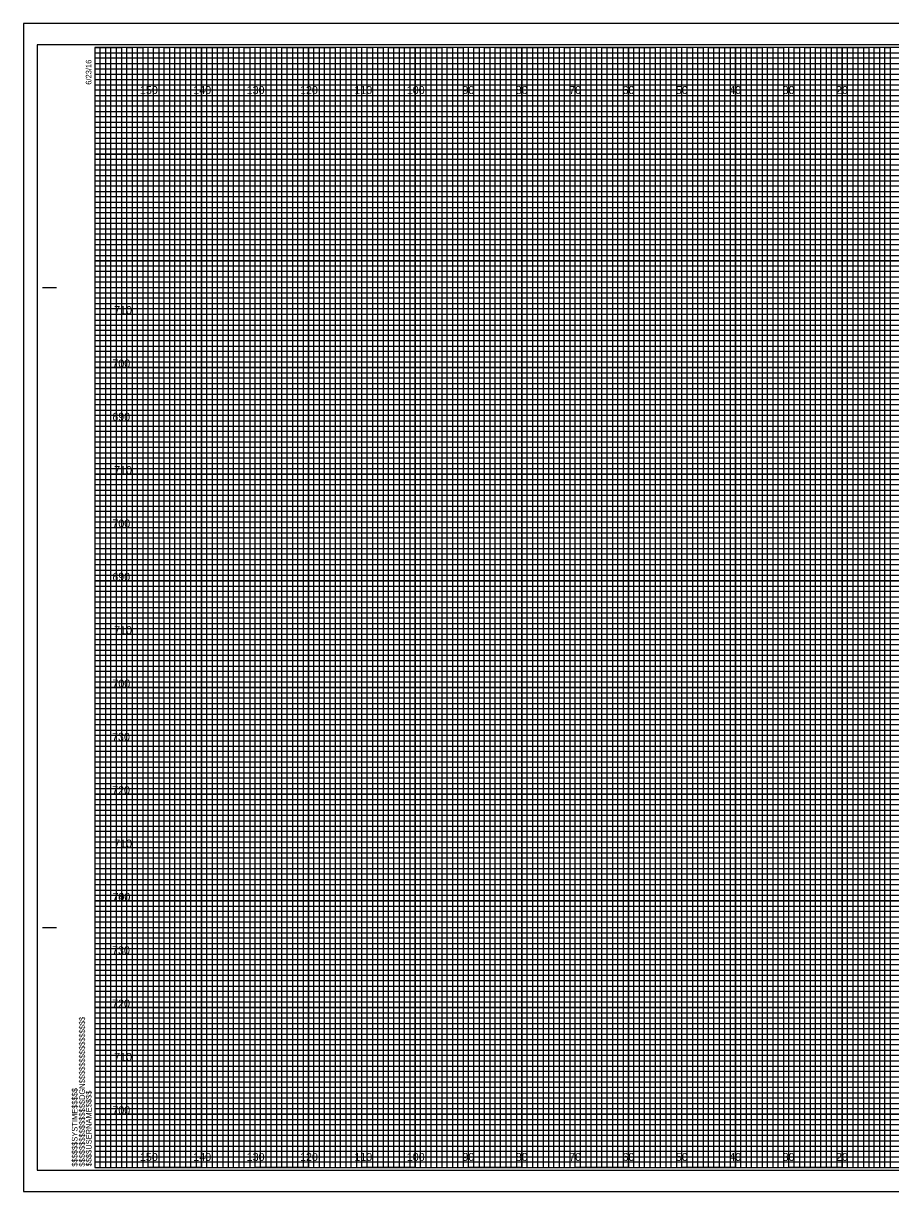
# Model space of a CAD drawing. Extents: x -13 to 323, y -4 to 434.
# Drawn here: x -13.4 to 149.1, y 215.5 to 434.5 of the extents above; entities that cross this region are included whole.
import ezdxf

# ---------------------------------------------------------------- set-up
doc = ezdxf.new("R2010")
doc.units = 0
for name, color, linetype in [('Exist XS Center Line Elevation Label', 7, 'Continuous'), ('Prop CMT Conc Surface', 7, 'Continuous'), ('Prop CMT Concrete Structures', 7, 'Continuous'), ('Prop CMT Pvmt Course 1 CG', 7, 'Continuous'), ('Prop CMT Pvmt Course 2', 7, 'Continuous'), ('Prop CMT Pvmt Course 3', 7, 'Continuous'), ('Prop CMT Pvmt Surface', 7, 'Continuous'), ('Prop CMT Subgrade Earthwork', 7, 'Continuous'), ('Prop XS Earthwork Shape', 7, 'Continuous'), ('Prop XS Elevation Labels', 7, 'Continuous'), ('Typical Curb CELL', 7, 'Continuous')]:
    doc.layers.add(name, color=color, linetype=linetype)

msp = doc.modelspace()

# ---------------------------------------------------------------- linework, layer by layer
at = {"layer": 'Exist XS Center Line Elevation Label'}
for p, q in [((0, 429), (260, 429)), ((260, 427.98), (0, 427.98)), ((0, 427.98), (0, 427)), ((0, 427), (260, 427)), ((260, 425.89), (0, 425.89)), ((0, 425.89), (0, 424)), ((0, 424), (320, 424))]:
    msp.add_line(p, q, dxfattribs=at)
for points in [[(0, 423), (270, 423), (320, 423), (320, 422), (0, 422)], [(0, 421), (320, 421), (320, 419), (0, 419)], [(0, 418), (320, 418), (320, 417), (0, 416.98)], [(0, 416), (320, 416), (320, 414), (0, 414)], [(0, 413), (320, 413), (320, 412), (0, 412)], [(0, 411), (320, 411), (320, 409), (0, 409)], [(0, 408), (320, 408), (320, 407), (0, 407)], [(0, 406), (320, 406), (320, 404), (0, 404)], [(0, 403), (320, 403), (320, 402), (0, 402)], [(0, 401), (320, 401), (320, 399), (0, 399)], [(0, 398), (320, 398), (320, 397), (0, 397)], [(0, 396), (320, 396), (320, 393.95), (320, 393), (320, 392), (0, 392)], [(0, 394), (320, 394), (320, 393), (0, 393)], [(0, 391), (320, 391), (320, 389), (0, 389.03)], [(0, 389.03), (320, 389), (320, 388), (0, 388)], [(0, 387), (320, 387), (320, 386), (0, 386)], [(0, 384), (320, 384), (320, 383), (0, 383)], [(0, 382), (320, 382), (320, 381), (0, 381)], [(-0.07, 378.89), (320, 378.89), (320, 377.88), (-0.07, 377.88)], [(0, 377), (320, 377), (320, 376), (0, 376)], [(0, 374), (320, 374), (320, 373), (0, 373)], [(0, 372), (320, 372), (320, 371), (0, 371)], [(0, 369), (320, 369), (320, 368), (0, 368)], [(0, 367), (320, 367), (320, 366), (0, 366)], [(0, 364), (320, 364), (320, 363), (0, 363)], [(0, 362), (320, 362), (320, 361), (0, 361)], [(0, 359), (320, 359), (319.99, 357.98), (0, 358)], [(0, 357), (320, 357), (320, 356), (0, 356)], [(0, 354), (320, 354), (320, 353), (0, 353)], [(0, 352), (320, 352), (320, 351), (0, 351)], [(0, 349), (320, 349), (320, 348), (0, 348)], [(0, 347), (320, 347), (320, 346), (0, 346)], [(0, 344), (320, 344), (320, 343), (0, 343)], [(0, 342), (320, 342), (320, 341), (0, 341)], [(0, 339), (320, 339), (320, 338), (0, 338)], [(0, 336.99), (320.07, 336.91), (320, 336), (0, 336)], [(0, 334), (320, 334), (320, 333), (0, 333)], [(0, 332), (320, 332), (320, 331), (0, 331)], [(0, 329), (320, 329), (320, 328), (0, 328)], [(0, 327), (320, 327), (320, 326), (0, 326)], [(0, 324), (320, 324), (320, 323), (0, 323)], [(0, 322), (320, 322), (320, 321), (0, 321)], [(0, 319), (320, 319), (320, 318), (0, 318)], [(0, 317), (320, 317), (320, 316), (0, 316)], [(0, 314), (320, 314), (320, 313), (0, 313)], [(0, 312), (320, 312), (320, 311), (0, 311)], [(0, 309), (320, 309), (320, 308), (0, 308)], [(0, 307), (320, 307), (320, 306), (0, 306)], [(0, 304), (320, 304), (320, 303), (0, 303)], [(0, 302), (320, 302), (320, 301), (0, 301)], [(0, 299), (320, 299), (319.99, 297.98), (0, 298)], [(0, 297), (320, 297), (320, 296), (0, 296)], [(0, 294), (320, 294), (320, 293), (0, 293)], [(0, 292), (320, 292), (320, 291), (0, 291)], [(0, 289), (320, 289), (320, 288), (0, 288)], [(0, 287), (320, 287), (320, 286), (0, 286)], [(0, 284), (320, 284), (320, 283), (0, 283)], [(0, 282), (320, 282), (320, 281), (0, 281)], [(0, 279), (320, 279), (320, 278), (0, 278)], [(0, 276.99), (320.07, 276.91), (320, 276), (0, 276)], [(0, 274), (320, 274), (320, 273), (0, 273)], [(0, 272), (320, 272), (320, 271), (0, 271)], [(0, 269), (320, 269), (320, 268), (0, 268)], [(0, 267), (320, 267), (320, 266), (0, 266)], [(0, 264), (320, 264), (320, 263), (0, 263)], [(0, 262), (320, 262), (320, 261), (0, 261)], [(0, 259), (320, 259), (320, 258), (0, 258)], [(0, 257), (320, 257), (320, 256), (0, 256)], [(0, 254), (320, 254), (320, 253), (0, 253)], [(0, 252), (320, 252), (320, 251), (0, 251)], [(0, 249), (320, 249), (320, 248), (0, 248)], [(0, 247), (320, 247), (320, 246), (0, 246)], [(0, 244), (320, 244), (320, 243), (0, 243)], [(0, 242), (320, 242), (320, 241), (0, 241)], [(0, 239), (320, 239), (320, 238), (0, 238)], [(0, 237), (320, 237), (320, 236), (0, 236)], [(0, 234), (320, 234), (320, 233), (0, 233)], [(0, 232), (320, 232), (320, 231), (0, 231)], [(0, 229), (320, 229), (320, 228), (0, 228)], [(0, 227), (320, 227), (320, 226), (0, 226)], [(0, 224), (320, 224), (320, 223), (0, 223)], [(0, 222), (320, 222), (320, 221), (0, 221)]]:
    msp.add_lwpolyline(points, dxfattribs=at)
at = {"layer": 'Prop CMT Conc Surface'}
for p, q in [((-9.8, 385), (-7.3, 385)), ((-9.7, 385), (-7.2, 385)), ((-9.8, 265), (-7.3, 265)), ((-9.7, 265), (-7.2, 265)), ((0, 220), (0, 220)), ((0, 220), (0, 220)), ((0, 220), (0, 220)), ((0, 220), (0, 220)), ((0, 220), (0, 220)), ((0, 220), (0, 220)), ((0, 220), (0, 220))]:
    msp.add_line(p, q, dxfattribs=at)
msp.add_lwpolyline([(320, 430), (0, 430), (0, 220), (320, 220)], close=True, dxfattribs=at)
at = {"layer": 'Prop CMT Concrete Structures'}
for p, q in [((10, 220), (10, 430)), ((20, 220), (20, 430)), ((30, 220), (30, 430)), ((40, 220), (40, 430)), ((50, 220), (50, 430)), ((60, 220), (60, 430)), ((70, 220), (70, 430)), ((80, 220), (80, 430)), ((90, 220), (90, 430)), ((100, 220), (100, 430)), ((110, 220), (110, 430)), ((120, 220), (120, 430)), ((130, 220), (130, 430)), ((140, 220), (140, 430)), ((0, 420), (320, 420)), ((0, 410), (320, 410)), ((0, 400), (320, 400)), ((0, 390), (320, 390)), ((0, 380), (320, 380)), ((0, 370), (320, 370)), ((0, 360), (320, 360)), ((0, 350), (320, 350)), ((0, 340), (320, 340)), ((0, 330), (320, 330)), ((0, 320), (320, 320)), ((0, 310), (320, 310)), ((0, 300), (320, 300)), ((0, 290), (320, 290)), ((0, 280), (320, 280)), ((0, 270), (320, 270)), ((0, 260), (320, 260)), ((0, 250), (320, 250)), ((0, 240), (320, 240)), ((0, 230), (320, 230))]:
    msp.add_line(p, q, dxfattribs=at)
at = {"layer": 'Prop CMT Pvmt Course 2'}
msp.add_lwpolyline([(-13.4, 215.5), (323.3, 215.5), (323.3, 434.5), (-13.4, 434.5)], close=True, dxfattribs=at)
at = {"layer": 'Prop CMT Pvmt Course 3'}
msp.add_lwpolyline([(-10.8, 219.5), (322.4, 219.5), (322.4, 430.5), (-10.8, 430.5)], close=True, dxfattribs=at)
at = {"layer": 'Prop CMT Pvmt Surface'}
for p, q in [((323.3, 434.5), (-13.4, 434.5)), ((-13.4, 434.5), (-13.4, 215.5)), ((-13.4, 215.5), (323.3, 215.5))]:
    msp.add_line(p, q, dxfattribs=at)
at = {"layer": 'Prop CMT Subgrade Earthwork'}
for points in [[(0, 220), (1, 220), (1, 430), (2, 430), (2, 220)], [(2, 220), (3, 220), (3, 430), (4, 430), (4, 220)], [(5, 220), (6, 220), (6, 430), (7, 430), (7, 220)], [(7, 220), (8, 220), (8, 430), (9, 430), (9, 220)], [(10, 220), (11, 220), (11, 430), (12, 430), (12, 220)], [(12, 220), (13, 220), (13, 430), (14, 430), (14, 220)], [(15, 220), (16, 220), (16, 430), (17, 430), (17, 220)], [(17, 220), (18, 220), (18, 430), (19, 430), (19, 220)], [(20, 220), (21, 220), (21, 430), (22, 430), (22, 220)], [(22, 220), (23, 220), (23, 430), (24, 430), (24, 220)], [(25, 220), (26, 220), (26, 430), (27, 430), (27, 220)], [(27, 220), (28, 220), (28, 430), (29, 430), (29, 220)], [(30, 220), (31, 220), (31, 430), (32, 430), (32, 220)], [(32, 220), (33, 220), (33, 430), (34, 430), (34, 220)], [(35, 220), (36, 220), (36, 430), (37, 430), (37, 220)], [(37, 220), (38, 220), (38, 430), (39, 430), (39, 220)], [(40, 220), (41, 220), (41, 430), (42, 430), (42, 220)], [(42, 220), (43, 220), (43, 430), (44, 430), (44, 220)], [(45, 220), (46, 220), (46, 430), (47, 430), (47, 220)], [(47, 220), (48, 220), (48, 430), (49, 430), (49, 220)], [(50, 220), (51, 220), (51, 430), (52, 430), (52, 220)], [(52, 220), (53, 220), (53, 430), (54, 430), (54, 220)], [(55, 220), (56, 220), (56, 430), (57, 430), (57, 220)], [(57, 220), (58, 220), (58, 430), (59, 430), (59, 220)], [(60, 220), (61, 220), (61, 430), (62, 430), (62, 220)], [(62, 220), (63, 220), (63, 430), (64, 430), (64, 220)], [(65, 220), (66, 220), (66, 430), (67, 430), (67, 220)], [(67, 220), (68, 220), (68, 430), (69, 430), (69, 220)], [(70, 220), (71, 220), (71, 430), (72, 430), (72, 220)], [(72, 220), (73, 220), (73, 430), (74, 430), (74, 220)], [(75, 220), (76, 220), (76, 430), (77, 430), (77, 220)], [(77, 220), (78, 220), (78, 430), (79, 430), (79, 220)], [(80, 220), (81, 220), (81, 430), (82, 430), (82, 220)], [(82, 220), (83, 220), (83, 430), (84, 430), (84, 220)], [(85, 220), (86, 220), (86, 430), (87, 430), (87, 220)], [(87, 220), (88, 220), (88, 430), (89, 430), (89, 220)], [(90, 220), (91, 220), (91, 430), (92, 430), (92, 220)], [(92, 220), (93, 220), (93, 430), (94, 430), (94, 220)], [(95, 220), (96, 220), (96, 430), (97, 430), (97, 220)], [(97, 220), (98, 220), (98, 430), (99, 430), (99, 220)], [(100, 220), (101, 220), (101, 430), (102, 430), (102, 220)], [(102, 220), (103, 220), (103, 430), (104, 430), (104, 220)], [(105, 220), (106, 220), (106, 430), (107, 430), (107, 220)], [(107, 220), (108, 220), (108, 430), (109, 430), (109, 220)], [(110, 220), (111, 220), (111, 430), (112, 430), (112, 220)], [(112, 220), (113, 220), (113, 430), (114, 430), (114, 220)], [(115, 220), (116, 220), (116, 430), (117, 430), (117, 220)], [(117, 220), (118, 220), (118, 430), (119, 430), (119, 220)], [(120, 220), (121, 220), (121, 430), (122, 430), (122, 220)], [(122, 220), (123, 220), (123, 430), (124, 430), (124, 220)], [(125, 220), (126, 220), (126, 430), (127, 430), (127, 220)], [(127, 220), (128, 220), (128, 430), (129, 430), (129, 220)], [(130, 220), (131, 220), (131, 430), (132, 430), (132, 220)], [(132, 220), (133, 220), (133, 430), (134, 430), (134, 220)], [(135, 220), (136, 220), (136, 430), (137, 430), (137, 220)], [(137, 220), (138, 220), (138, 430), (139, 430), (139, 220)], [(140, 220), (141, 220), (141, 430), (142, 430), (142, 220)], [(142, 220), (143, 220), (143, 430), (144, 430), (144, 220)], [(145, 220), (146, 220), (146, 430), (147, 430), (147, 220)], [(147, 220), (148, 220), (148, 430), (149, 430), (149, 220)]]:
    msp.add_lwpolyline(points, dxfattribs=at)
at = {"layer": 'Prop XS Elevation Labels'}
for p, q in [((10, 430), (0, 430)), ((10, 220), (10, 430)), ((30, 430), (20, 430)), ((20, 430), (20, 220)), ((30, 220), (30, 430)), ((50, 430), (40, 430)), ((40, 430), (40, 220)), ((50, 220), (50, 430)), ((70, 430), (60, 430)), ((60, 430), (60, 220)), ((70, 220), (70, 430)), ((90, 430), (80, 430)), ((80, 430), (80, 220)), ((90, 220), (90, 430)), ((110, 430), (100, 430)), ((100, 430), (100, 220)), ((110, 220), (110, 430)), ((130, 430), (120, 430)), ((120, 430), (120, 220)), ((130, 220), (130, 430)), ((150, 430), (140, 430)), ((140, 430), (140, 220)), ((20, 220), (10, 220)), ((40, 220), (30, 220)), ((60, 220), (50, 220)), ((80, 220), (70, 220)), ((100, 220), (90, 220)), ((120, 220), (110, 220)), ((140, 220), (130, 220))]:
    msp.add_line(p, q, dxfattribs=at)
for points in [[(0, 420), (320, 420), (320, 410), (0, 410)], [(0, 400), (320, 400), (320, 390), (0, 390)], [(0, 380), (320, 380), (320, 370), (0, 370)], [(0, 360), (320, 360), (320, 350), (0, 350)], [(0, 340), (320, 340), (320, 330), (0, 330)], [(0, 320), (320, 320), (320, 310), (0, 310)], [(0, 300), (320, 300), (320, 290), (0, 290)], [(0, 280), (320, 280), (320, 270), (0, 270)], [(0, 260), (320, 260), (320, 250), (0, 250)], [(0, 240), (320, 240), (320, 230), (0, 230)]]:
    msp.add_lwpolyline(points, dxfattribs=at)
at = {"layer": 'Typical Curb CELL'}
for points in [[(0, 430), (5, 430), (5, 220), (15, 220), (15, 430), (25, 430), (25, 220), (35, 220), (35, 430), (45, 430), (45, 220), (55, 220), (55, 430), (65, 430), (65, 220), (75, 220), (75, 430), (85, 430), (85, 220), (95, 220), (95, 430), (105, 430), (105, 220), (115, 220), (115, 430), (125, 430), (125, 220), (135, 220), (135, 430), (145, 430), (145, 220), (155, 220)], [(0, 425), (275, 425)], [(0, 405), (320, 405), (320, 415), (0, 415)], [(0, 385), (320, 385), (320, 395), (0, 395)], [(0, 365), (320, 365), (320, 375), (0, 375)], [(0, 345), (320, 345), (320, 355), (0, 355)], [(0, 325), (320, 325), (320, 335), (0, 335)], [(0, 305), (320, 305), (320, 315), (0, 315)], [(0, 285), (320, 285), (320, 295), (0, 295)], [(0, 265), (320, 265), (320, 275), (0, 275)], [(0, 245), (320, 245), (320, 255), (0, 255)], [(0, 225), (320, 225), (320, 235), (0, 235)]]:
    msp.add_lwpolyline(points, dxfattribs=at)

# ---------------------------------------------------------------- texts
at = {"layer": 'Prop CMT Conc Surface'}
for s, p in [('6/23/16', (-0.65, 423)), ('$$$$$$$$$$$$$$$$DGN$$$$$$$$$$$$$$$$', (-1.88, 220.18)), ('$$$$$$SYSTIME$$$$$', (-3.26, 220.18)), ('$$$$USERNAME$$$$', (-0.62, 220.23))]:
    msp.add_text(s, height=1.05, rotation=90, dxfattribs=at).set_placement(p)
at = {"layer": 'Prop CMT Pvmt Course 1 CG'}
for s, p in [('710', (3.61, 380)), ('700', (3.28, 370)), ('690', (3.26, 360)), ('710', (3.61, 350)), ('700', (3.28, 340)), ('690', (3.26, 330)), ('710', (3.61, 320)), ('700', (3.28, 310)), ('730', (3.22, 300)), ('720', (3.23, 290)), ('710', (3.61, 280)), ('700', (3.28, 270)), ('740', (3.3, 270)), ('730', (3.22, 260)), ('720', (3.23, 250)), ('710', (3.61, 240)), ('700', (3.28, 230))]:
    msp.add_text(s, height=1.5, dxfattribs=at).set_placement(p)
at = {"layer": 'Prop XS Earthwork Shape'}
for s, p in [('150', (8.44, 421.25)), ('140', (18.44, 421.25)), ('130', (28.44, 421.25)), ('120', (38.44, 421.25)), ('110', (48.62, 421.25)), ('100', (58.44, 421.25)), ('90', (68.86, 421.25)), ('80', (78.86, 421.25)), ('70', (88.86, 421.25)), ('60', (98.86, 421.25)), ('50', (108.86, 421.25)), ('40', (118.86, 421.25)), ('30', (128.86, 421.25)), ('20', (138.86, 421.25)), ('150', (8.44, 221.25)), ('140', (18.44, 221.25)), ('130', (28.44, 221.25)), ('120', (38.44, 221.25)), ('110', (48.62, 221.25)), ('100', (58.44, 221.25)), ('90', (68.86, 221.25)), ('80', (78.86, 221.25)), ('70', (88.86, 221.25)), ('60', (98.86, 221.25)), ('50', (108.86, 221.25)), ('40', (118.86, 221.25)), ('30', (128.86, 221.25)), ('20', (138.86, 221.25))]:
    msp.add_text(s, height=1.5, dxfattribs=at).set_placement(p)

doc.saveas('drawing.dxf')
